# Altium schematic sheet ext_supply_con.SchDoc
size A3; DocumentNumber: 13; SheetNumber: 13; SheetTotal: 15; SheetDescription: External Power Supply Connector
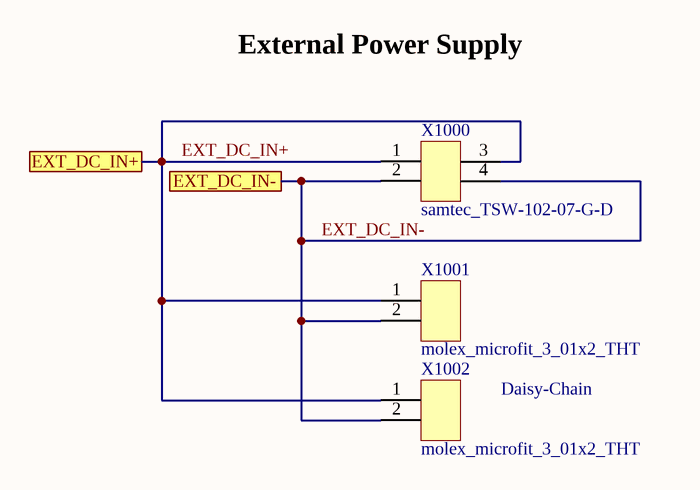
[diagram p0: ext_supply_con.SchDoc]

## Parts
X1000  samtec_TSW-102-07-G-D  [Pinheader_2.54_2x2]
X1001  molex_microfit_3_01x2_THT  [MOLEX_MICROFIT_01x2_THT]
X1002  molex_microfit_3_01x2_THT  [MOLEX_MICROFIT_01x2_THT]

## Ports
EXT_DC_IN+, EXT_DC_IN-

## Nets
EXT_DC_IN+: X1000.1 X1000.3 X1001.1 X1002.1 ; port EXT_DC_IN+
EXT_DC_IN-: X1000.2 X1000.4 X1001.2 X1002.2 ; port EXT_DC_IN-

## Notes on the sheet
- External Power Supply
- Daisy-Chain

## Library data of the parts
X1000 = samtec_TSW-102-07-G-D: Board-To-Board Connector, Vertical, 2.54 mm, 4 Contacts, Header, TSW Series, Through Hole, 2 Rows; Manufacturer: Samtec; Circuits: 4; Rated Voltage: 500V AC mated with SSW; Automotive Qualified: False
X1001 X1002 = molex_microfit_3_01x2_THT: Micro-Fit 3.0 Right Angle Header, 3.00mm Pitch, Dual Row, 2 Circuits, with Snap-in Plastic Peg PCB Lock, Tin, Glow Wire Capable, Black, 43045-0200; Manufacturer: Molex; Circuits: 2; Rated Voltage: 600V; Rated Current: 8.5A; Automotive Qualified: False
